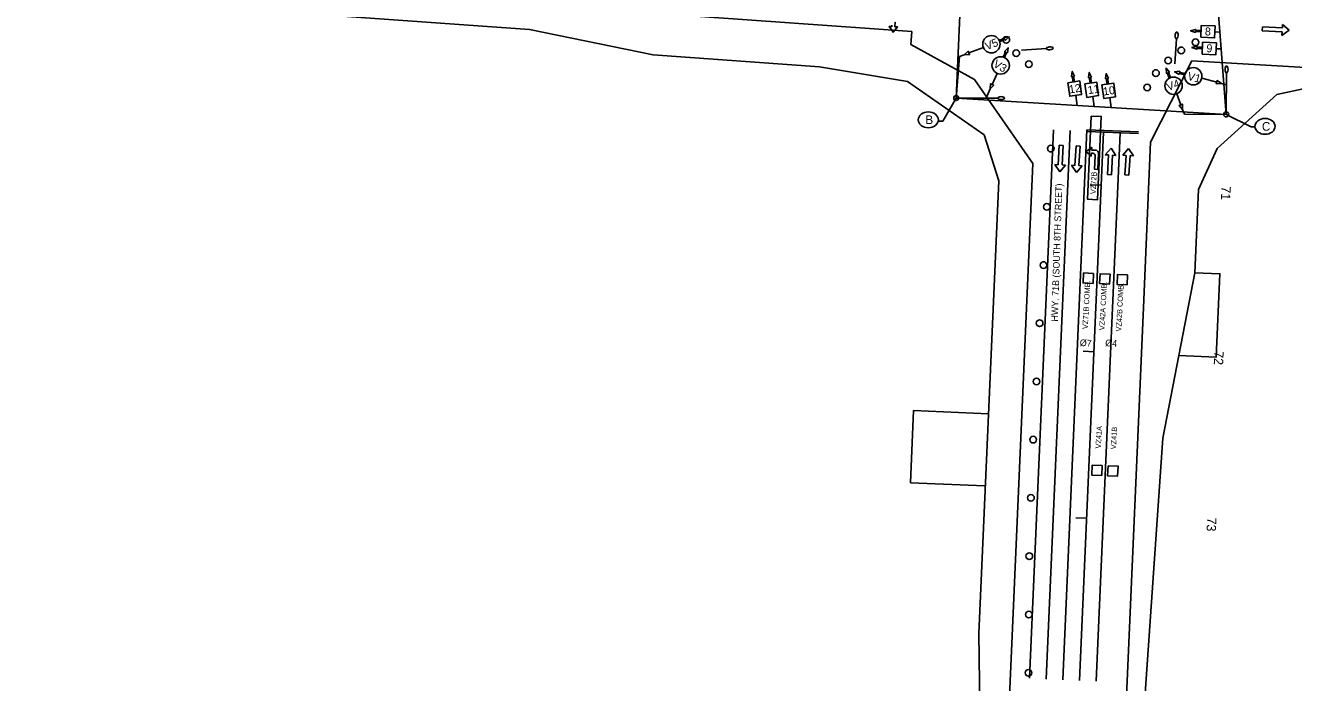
# Model space of a CAD drawing. Extents: x 0 to 1361828, y 0 to 1470398.
# Drawn here: x 685616 to 686377, y 734431 to 734825 of the extents above; entities that cross this region are included whole.
import ezdxf

# ---------------------------------------------------------------- set-up
doc = ezdxf.new("R2010")
doc.units = 0
for name, color, linetype in [('$', 7, 'Continuous'), ('BASE', 7, 'Continuous'), ('MOT Stage 1', 7, 'Continuous'), ('MOT Stage 1 Lanes', 7, 'Continuous'), ('R_Horz Alg Station', 7, 'Continuous'), ('RW-EX', 7, 'Continuous'), ('RW-PR', 7, 'Continuous'), ('SIGNAL-PLAN VIEW LABLES', 7, 'Continuous'), ('SIGNAL-PR', 7, 'Continuous'), ('SIGNAL-PR$', 7, 'Continuous'), ('TITEXT', 7, 'Continuous'), ('Video-Zones-pr', 7, 'Continuous')]:
    doc.layers.add(name, color=color, linetype=linetype)

# ---------------------------------------------------------------- blocks, each defined once
blk = doc.blocks.new('SARROW_212')
at = {"layer": 'MOT Stage 1'}
for p, q in [((0, 0), (-6, 0)), ((0, -29.4), (0, 0)), ((-6, -29.4), (-6, 0)), ((-6, -29.4), (-11, -29.4)), ((-3, -39.8), (-11, -29.4)), ((5, -29.4), (-3, -39.8)), ((5, -29.4), (0, -29.4))]:
    blk.add_line(p, q, dxfattribs=at)
blk = doc.blocks.new('SARROW_217')
at = {"layer": 'MOT Stage 1'}
for p, q in [((-6, -29.4), (-6, 0)), ((0, 0), (-6, 0)), ((0, -29.4), (0, 0)), ((-6, -29.4), (-11, -29.4)), ((-3, -39.8), (-11, -29.4)), ((5, -29.4), (-3, -39.8)), ((5, -29.4), (0, -29.4))]:
    blk.add_line(p, q, dxfattribs=at)
blk = doc.blocks.new('SARROW_218')
at = {"layer": 'MOT Stage 1'}
for p, q in [((0, 0), (-6, 0)), ((0, -29.4), (0, 0)), ((-6, -29.4), (-6, 0)), ((-6, -29.4), (-11, -29.4)), ((-3, -39.8), (-11, -29.4)), ((5, -29.4), (-3, -39.8)), ((5, -29.4), (0, -29.4))]:
    blk.add_line(p, q, dxfattribs=at)
blk = doc.blocks.new('SARROW_219')
at = {"layer": 'MOT Stage 1'}
for p, q in [((-6, -29.4), (-6, 0)), ((0, 0), (-6, 0)), ((0, -29.4), (0, 0)), ((-6, -29.4), (-11, -29.4)), ((-3, -39.8), (-11, -29.4)), ((5, -29.4), (-3, -39.8)), ((5, -29.4), (0, -29.4))]:
    blk.add_line(p, q, dxfattribs=at)
blk = doc.blocks.new('SARROW_220')
at = {"layer": 'MOT Stage 1'}
for p, q in [((-6, -29.4), (-6, 0)), ((0, 0), (-6, 0)), ((0, -29.4), (0, 0)), ((-6, -29.4), (-11, -29.4)), ((-3, -39.8), (-11, -29.4)), ((5, -29.4), (-3, -39.8)), ((5, -29.4), (0, -29.4))]:
    blk.add_line(p, q, dxfattribs=at)
blk = doc.blocks.new('BAREL_1874')
at = {"layer": 'MOT Stage 1'}
blk.add_circle((0, 0), 2.88, dxfattribs=at)
blk = doc.blocks.new('BAREL_1875')
at = {"layer": 'MOT Stage 1'}
blk.add_circle((0, 0), 2.88, dxfattribs=at)
blk = doc.blocks.new('BAREL_1876')
at = {"layer": 'MOT Stage 1'}
blk.add_circle((0, 0), 2.88, dxfattribs=at)
blk = doc.blocks.new('BAREL_1877')
at = {"layer": 'MOT Stage 1'}
blk.add_circle((0, 0), 2.88, dxfattribs=at)
blk = doc.blocks.new('BAREL_1878')
at = {"layer": 'MOT Stage 1'}
blk.add_circle((0, 0), 2.88, dxfattribs=at)
blk = doc.blocks.new('BAREL_1879')
at = {"layer": 'MOT Stage 1'}
blk.add_circle((0, 0), 2.88, dxfattribs=at)
blk = doc.blocks.new('BAREL_1880')
at = {"layer": 'MOT Stage 1'}
blk.add_circle((0, 0), 2.88, dxfattribs=at)
blk = doc.blocks.new('BAREL_1881')
at = {"layer": 'MOT Stage 1'}
blk.add_circle((0, 0), 2.88, dxfattribs=at)
blk = doc.blocks.new('BAREL_1882')
at = {"layer": 'MOT Stage 1'}
blk.add_circle((0, 0), 2.88, dxfattribs=at)
blk = doc.blocks.new('BAREL_1883')
at = {"layer": 'MOT Stage 1'}
blk.add_circle((0, 0), 2.88, dxfattribs=at)
blk = doc.blocks.new('BAREL_1887')
at = {"layer": 'MOT Stage 1'}
blk.add_circle((0, 0), 2.88, dxfattribs=at)
blk = doc.blocks.new('BAREL_1888')
at = {"layer": 'MOT Stage 1'}
blk.add_circle((0, 0), 2.88, dxfattribs=at)
blk = doc.blocks.new('BAREL_1889')
at = {"layer": 'MOT Stage 1'}
blk.add_circle((0, 0), 2.88, dxfattribs=at)
blk = doc.blocks.new('BAREL_1890')
at = {"layer": 'MOT Stage 1'}
blk.add_circle((0, 0), 2.88, dxfattribs=at)

msp = doc.modelspace()

# ---------------------------------------------------------------- linework, layer by layer
at = {"layer": '$'}
for p, q in [((686174.71, 734781.59), (686176.73, 734806.51)), ((686336.65, 734771.74), (686336.84, 734796.74)), ((686174.71, 734781.59), (686199.71, 734781.52)), ((686336.65, 734771.74), (686311.65, 734771.81))]:
    msp.add_line(p, q, dxfattribs=at)
for points in [[(686174.71, 734781.59), (686181.53, 734935.33)], [(686181.53, 734935.33), (686306.22, 734921.76), (686326.56, 734902.37), (686336.65, 734771.74), (686174.71, 734781.59)]]:
    msp.add_lwpolyline(points, dxfattribs=at)
for centre in [(686174.71, 734781.59), (686336.65, 734771.74)]:
    msp.add_circle(centre, 1.5, dxfattribs=at)
for centre, major_axis in [((686336.86, 734798.76), (-0.02, -2.02)), ((686201.73, 734781.51), (-2.02, 0.01))]:
    msp.add_ellipse(centre, major_axis=major_axis, ratio=0.447722, dxfattribs=at)
at = {"layer": 'MOT Stage 1'}
for points in [[(686138.09, 734826.75), (686138.11, 734827.07), (686137.96, 734824.32), (686139.56, 734824.23), (686136.83, 734821.05), (686134.45, 734824.5), (686136.05, 734824.42), (686136.09, 734825.25)], [(686258.32, 734750.22), (686258.64, 734750.2), (686255.89, 734750.35), (686255.98, 734751.95), (686252.52, 734749.57), (686255.7, 734746.84), (686255.79, 734748.43), (686256.62, 734748.39)], [(686258.13, 734746.71), (686257.71, 734738.86), (686259.63, 734738.76)], [(686259.63, 734738.76), (686260.15, 734748.52), (686260.13, 734748.2)]]:
    msp.add_lwpolyline(points, dxfattribs=at)
for centre, radius in [((686256.53, 734746.79), 1.6), ((686258.22, 734748.3), 1.92)]:
    msp.add_arc(centre, radius, 356.9293, 86.9293, dxfattribs=at)
at = {"layer": 'MOT Stage 1 Lanes'}
for p, q in [((686233.08, 734762.48), (686218.74, 734433.3)), ((686243.07, 734762.04), (686228.73, 734432.86)), ((686253.1, 734762.54), (686238.72, 734432.43)), ((686263.05, 734761.17), (686248.71, 734431.99)), ((686253.06, 734761.54), (686284.04, 734760.3)), ((686253.1, 734762.54), (686284.1, 734761.3)), ((686273.04, 734760.74), (686258.7, 734431.56))]:
    msp.add_line(p, q, dxfattribs=at)
at = {"layer": 'R_Horz Alg Station'}
for points in [[(686261.82, 734729.2), (686255.16, 734729.49)], [(686257.47, 734629.3), (686250.81, 734629.59)], [(686253.12, 734529.39), (686246.46, 734529.68)]]:
    msp.add_lwpolyline(points, dxfattribs=at)
at = {"layer": 'RW-EX'}
for p, q in [((685615.93, 734859.48), (686148.06, 734821.44)), ((686148.06, 734821.44), (686147.62, 734813.65)), ((686147.62, 734813.65), (686185.65, 734792.74)), ((686291.31, 734755.12), (686316.03, 734803.86)), ((686316.03, 734803.86), (686801.87, 734775.88)), ((686185.65, 734792.74), (686220.69, 734742.33)), ((686286.99, 734655.89), (686291.31, 734755.12)), ((686220.69, 734742.33), (686208.34, 734458.85)), ((686273.67, 734350.1), (686286.99, 734655.89)), ((686208.34, 734458.85), (686203.74, 734353.15))]:
    msp.add_line(p, q, dxfattribs=at)
at = {"layer": 'RW-PR'}
for p, q in [((686149.16, 734593.98), (686147.28, 734550.7)), ((686194.12, 734592.02), (686149.16, 734593.98))]:
    msp.add_line(p, q, dxfattribs=at)
for points in [[(685416.49, 734855.93), (685615.28, 734844.49), (685918.84, 734822.79), (685992.93, 734807.46), (686092.68, 734800.33), (686145.51, 734791.54), (686191.41, 734759.48), (686200.21, 734731.89), (686188.38, 734460.16), (686189.54, 734372.01), (686196.02, 734332.97)], [(686331.18, 734751.21), (686367.05, 734783.79), (686404.18, 734791.67), (686502.4, 734786.01), (686652.56, 734784.48)], [(686275.87, 734328.55), (686284.89, 734377.87), (686298.59, 734577.46), (686317.93, 734676.71), (686320.1, 734726.66), (686331.18, 734751.21)], [(686317.93, 734676.71), (686332.91, 734676.06), (686330.74, 734626.11), (686308.26, 734627.09)], [(686147.28, 734550.7), (686191.81, 734548.76), (686192.24, 734548.74)]]:
    msp.add_lwpolyline(points, dxfattribs=at)
at = {"layer": 'SIGNAL-PLAN VIEW LABLES'}
for points in [[(686318.25, 734822.3), (686318.27, 734822.8), (686315.29, 734821.99), (686318.2, 734820.96), (686318.22, 734821.46), (686321.58, 734821.34), (686321.61, 734822.18), (686318.25, 734822.3)], [(686321.61, 734822.18), (686318.25, 734822.3), (686318.27, 734822.8), (686315.29, 734821.99), (686318.2, 734820.96), (686318.22, 734821.46), (686321.58, 734821.34)], [(686332.84, 734821.1), (686329.84, 734821.28)], [(686204.02, 734816.71), (686204.22, 734816.24), (686206.59, 734818.22), (686203.51, 734817.95), (686203.7, 734817.48), (686200.6, 734816.2), (686200.92, 734815.42), (686204.02, 734816.71)], [(686200.92, 734815.42), (686204.02, 734816.71), (686204.22, 734816.24), (686206.59, 734818.22), (686203.51, 734817.95), (686203.7, 734817.48), (686200.6, 734816.2)], [(686176.73, 734806.51), (686179.58, 734807.59)], [(686182.35, 734808.63), (686191.04, 734811.92)], [(686204.99, 734808.92), (686205.45, 734808.71), (686205.81, 734811.78), (686203.76, 734809.47), (686204.22, 734809.26), (686202.85, 734806.2), (686203.62, 734805.85), (686204.99, 734808.92)], [(686203.62, 734805.85), (686204.99, 734808.92), (686205.45, 734808.71), (686205.81, 734811.78), (686203.76, 734809.47), (686204.22, 734809.26), (686202.85, 734806.2)], [(686319.03, 734812.24), (686319.05, 734812.75), (686316.07, 734811.93), (686318.98, 734810.9), (686319, 734811.4), (686322.36, 734811.28), (686322.39, 734812.12), (686319.03, 734812.24)], [(686322.39, 734812.12), (686319.03, 734812.24), (686319.05, 734812.75), (686316.07, 734811.93), (686318.98, 734810.9), (686319, 734811.4), (686322.36, 734811.28)], [(686333.62, 734811.02), (686330.62, 734811.2)], [(686302.09, 734796.97), (686302.56, 734797.15), (686300.64, 734799.57), (686300.84, 734796.48), (686301.31, 734796.67), (686302.53, 734793.53), (686303.31, 734793.84), (686302.09, 734796.97)], [(686303.31, 734793.84), (686302.09, 734796.97), (686302.56, 734797.15), (686300.64, 734799.57), (686300.84, 734796.48), (686301.31, 734796.67), (686302.53, 734793.53)], [(686196.3, 734789.71), (686199.32, 734796.34)], [(686245.17, 734794.68), (686245.67, 734794.75), (686244.34, 734797.54), (686243.84, 734794.49), (686244.34, 734794.56), (686244.82, 734791.24), (686245.65, 734791.35), (686245.17, 734794.68)], [(686245.65, 734791.35), (686245.17, 734794.68), (686245.67, 734794.75), (686244.34, 734797.54), (686243.84, 734794.49), (686244.34, 734794.56), (686244.82, 734791.24)], [(686255.36, 734794.06), (686255.86, 734794.13), (686254.53, 734796.92), (686254.03, 734793.87), (686254.53, 734793.94), (686255.01, 734790.62), (686255.84, 734790.73), (686255.36, 734794.06)], [(686255.84, 734790.73), (686255.36, 734794.06), (686255.86, 734794.13), (686254.53, 734796.92), (686254.03, 734793.87), (686254.53, 734793.94), (686255.01, 734790.62)], [(686265.56, 734793.44), (686266.05, 734793.51), (686264.72, 734796.3), (686264.23, 734793.25), (686264.72, 734793.32), (686265.2, 734790), (686266.03, 734790.11), (686265.56, 734793.44)], [(686266.03, 734790.11), (686265.56, 734793.44), (686266.05, 734793.51), (686264.72, 734796.3), (686264.23, 734793.25), (686264.72, 734793.32), (686265.2, 734790)], [(686308.65, 734797.12), (686308.77, 734797.61), (686305.68, 734797.38), (686308.35, 734795.81), (686308.46, 734796.3), (686311.74, 734795.54), (686311.93, 734796.36), (686308.65, 734797.12)], [(686311.93, 734796.36), (686308.65, 734797.12), (686308.77, 734797.61), (686305.68, 734797.38), (686308.35, 734795.81), (686308.46, 734796.3), (686311.74, 734795.54)], [(686330.99, 734791.09), (686322, 734793.47)], [(686192.61, 734781.54), (686195.07, 734787.02)], [(686247.26, 734777.18), (686246.41, 734783.12)], [(686309.49, 734777.49), (686306.96, 734784.13)], [(686336.79, 734789.55), (686333.85, 734790.33)], [(686174.71, 734781.59), (686166.62, 734767.62), (686163.91, 734767.62)], [(686257.45, 734776.56), (686256.6, 734782.5)], [(686267.64, 734775.94), (686266.79, 734781.88)], [(686311.65, 734771.81), (686310.54, 734774.73)], [(686336.65, 734771.74), (686351.65, 734764.35), (686353.93, 734764.35)]]:
    msp.add_lwpolyline(points, dxfattribs=at)
for points in [[(686321.47, 734818.03), (686321.71, 734825.16), (686329.97, 734824.88), (686329.72, 734817.68)], [(686322.24, 734807.95), (686322.49, 734815.08), (686330.75, 734814.8), (686330.5, 734807.6)], [(686179.58, 734807.59), (686181.99, 734809.61), (686182.71, 734807.66)], [(686241.74, 734790.79), (686248.8, 734791.81), (686249.97, 734783.63), (686242.84, 734782.61)], [(686251.93, 734790.17), (686258.99, 734791.19), (686260.16, 734783.01), (686253.03, 734781.99)], [(686262.12, 734789.55), (686269.18, 734790.57), (686270.36, 734782.39), (686263.22, 734781.37)], [(686333.85, 734790.33), (686330.71, 734790.08), (686331.26, 734792.09)], [(686195.07, 734787.02), (686195.36, 734790.16), (686197.24, 734789.27)], [(686310.54, 734774.73), (686308.51, 734777.13), (686310.46, 734777.85)]]:
    msp.add_lwpolyline(points, close=True, dxfattribs=at)
for centre in [(686195.86, 734813.9), (686201.4, 734801.13), (686316.93, 734794.66), (686305.09, 734788.99)]:
    msp.add_circle(centre, 5.21, dxfattribs=at)
for centre in [(686158.01, 734768.53), (686359.94, 734764.55)]:
    msp.add_ellipse(centre, major_axis=(-6.02, 0), ratio=0.790685, dxfattribs=at)
at = {"layer": 'SIGNAL-PR'}
for p, q in [((686305.93, 734802.14), (686306.79, 734817.12)), ((686213.84, 734810.31), (686228.81, 734811.28))]:
    msp.add_line(p, q, dxfattribs=at)
for centre, major_axis in [((686306.91, 734819.14), (-0.12, -2.02)), ((686230.83, 734811.41), (-2.02, -0.13))]:
    msp.add_ellipse(centre, major_axis=major_axis, ratio=0.447722, dxfattribs=at)
at = {"layer": 'Video-Zones-pr'}
for points in [[(686255.76, 734770.77), (686253.55, 734720.82), (686259.54, 734720.55), (686261.76, 734770.5)], [(686266.98, 734675.91), (686260.98, 734676.15), (686260.74, 734670.16), (686266.74, 734669.92)], [(686277.41, 734675.5), (686271.42, 734675.74), (686271.18, 734669.74), (686277.17, 734669.5)], [(686262.28, 734561.01), (686256.29, 734561.25), (686256.05, 734555.25), (686262.04, 734555.01)]]:
    msp.add_lwpolyline(points, close=True, dxfattribs=at)
for points in [[(686257.12, 734676.31), (686251.12, 734676.57), (686250.86, 734670.57), (686256.85, 734670.31), (686257.12, 734676.31)], [(686265.77, 734560.87), (686265.54, 734554.87), (686271.53, 734554.63), (686271.77, 734560.63), (686265.77, 734560.87)]]:
    msp.add_lwpolyline(points, dxfattribs=at)

# ---------------------------------------------------------------- block references
at = {"layer": 'MOT Stage 1'}
for name, p, xscale, yscale, rotation in [('SARROW_212', (686358.38, 734824.3), 0.4075873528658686, 0.40758735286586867, 86.96871170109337), ('BAREL_1890', (686204.76, 734816.49), 0.6945420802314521, 0.6945420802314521, 95.09787459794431), ('BAREL_1889', (686318.23, 734815.02), 0.6945420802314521, 0.6945420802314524, -5.7347013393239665), ('BAREL_1889', (686210.75, 734808.48), 0.6945420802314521, 0.6945420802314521, 95.09787459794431), ('BAREL_1888', (686301.82, 734804.05), 0.6945420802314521, 0.6945420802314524, -5.7347013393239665), ('BAREL_1889', (686309.73, 734810.17), 0.6945420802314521, 0.6945420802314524, -5.7347013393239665), ('BAREL_1888', (686218.24, 734801.86), 0.6945420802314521, 0.6945420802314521, 95.09787459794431), ('BAREL_1887', (686294.52, 734796.57), 0.6945420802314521, 0.6945420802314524, -5.7347013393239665), ('BAREL_1887', (686289.3, 734787.9), 0.6945420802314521, 0.6945420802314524, -5.7347013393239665), ('BAREL_1883', (686231.48, 734751.2), 0.6945420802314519, 0.6945420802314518, 87.04179557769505), ('SARROW_220', (686238.97, 734753.14), 0.39999999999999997, 0.4, -3.359310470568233), ('SARROW_219', (686249.04, 734752.77), 0.39999999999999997, 0.4, -3.359310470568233), ('SARROW_218', (686267.86, 734735.55), 0.39999999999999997, -0.39999999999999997, -3.359310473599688), ('SARROW_217', (686278.33, 734735.25), 0.39999999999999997, -0.39999999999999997, -3.359310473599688), ('BAREL_1882', (686229.04, 734716.28), 0.6945420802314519, 0.6945420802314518, 87.04179557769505), ('BAREL_1881', (686227.11, 734681.33), 0.6945420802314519, 0.6945420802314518, 87.04179557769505), ('BAREL_1880', (686224.78, 734646.41), 0.6945420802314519, 0.6945420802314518, 87.04179557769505), ('BAREL_1879', (686222.85, 734611.47), 0.6945420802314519, 0.6945420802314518, 87.04179557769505), ('BAREL_1878', (686220.91, 734576.52), 0.6945420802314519, 0.6945420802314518, 87.04179557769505), ('BAREL_1877', (686219.56, 734541.55), 0.6945420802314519, 0.6945420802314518, 87.04179557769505), ('BAREL_1876', (686218.58, 734506.56), 0.6945420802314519, 0.6945420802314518, 87.04179557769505), ('BAREL_1875', (686218.27, 734471.56), 0.6945420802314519, 0.6945420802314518, 87.04179557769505), ('BAREL_1874', (686218.08, 734436.56), 0.6945420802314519, 0.6945420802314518, 87.04179557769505)]:
    msp.add_blockref(name, p, dxfattribs=dict(at, xscale=xscale, yscale=yscale, rotation=rotation))

# ---------------------------------------------------------------- texts
at = {"layer": '$'}
for s, p in [('71', (686333.87, 734728.73)), ('72', (686329.56, 734629.79)), ('73', (686325.21, 734529.88))]:
    msp.add_text(s, height=5.6, rotation=267.50583, dxfattribs=at).set_placement(p)
at = {"layer": 'BASE'}
msp.add_text('HWY. 71B (SOUTH 8TH STREET)', height=4, rotation=88.15245, dxfattribs=at).set_placement((686235.68, 734647.35))
at = {"layer": 'SIGNAL-PLAN VIEW LABLES'}
for s, rotation, p in [('8', 357.04142, (686323.79, 734819.21)), ('V5', 21.58786, (686193.13, 734810.23)), ('9', 357.04142, (686324.68, 734809.13)), ('V3', 329.19871, (686196.53, 734800.73)), ('V4', 20.05696, (686301.94, 734785.75)), ('V1', 346.04012, (686313.14, 734792.55)), ('12', 8.14498, (686242.7, 734784.33)), ('11', 8.14498, (686253.95, 734783.86)), ('10', 8.14498, (686263.12, 734783.09))]:
    msp.add_text(s, height=4.8, rotation=rotation, dxfattribs=at).set_placement(p)
for s, p in [('B', (686156.27, 734765.93)), ('C', (686358.08, 734761.95))]:
    msp.add_text(s, height=5.2, dxfattribs=at).set_placement(p)
at = {"layer": 'SIGNAL-PR$'}
for s, rotation, p in [('VZ72B', 87.43709, (686258.38, 734723.86)), ('VZ71B COMB.', 86.93491, (686253.6, 734642.82)), ('VZ42A COMB.', 86.93491, (686263.65, 734642.11)), ('VZ42B COMB.', 86.93491, (686273.68, 734641.37)), ('VZ41A', 86.93491, (686261.44, 734571.15)), ('VZ41B', 86.93491, (686270.52, 734570.65))]:
    msp.add_text(s, height=3.2, rotation=rotation, dxfattribs=at).set_placement(p)
at = {"layer": 'TITEXT'}
for s, p in [('%%C7', (686248.75, 734632.79)), ('%%C4', (686264.01, 734632.72))]:
    msp.add_text(s, height=4, rotation=356.2723, dxfattribs=at).set_placement(p)

doc.saveas('drawing.dxf')
